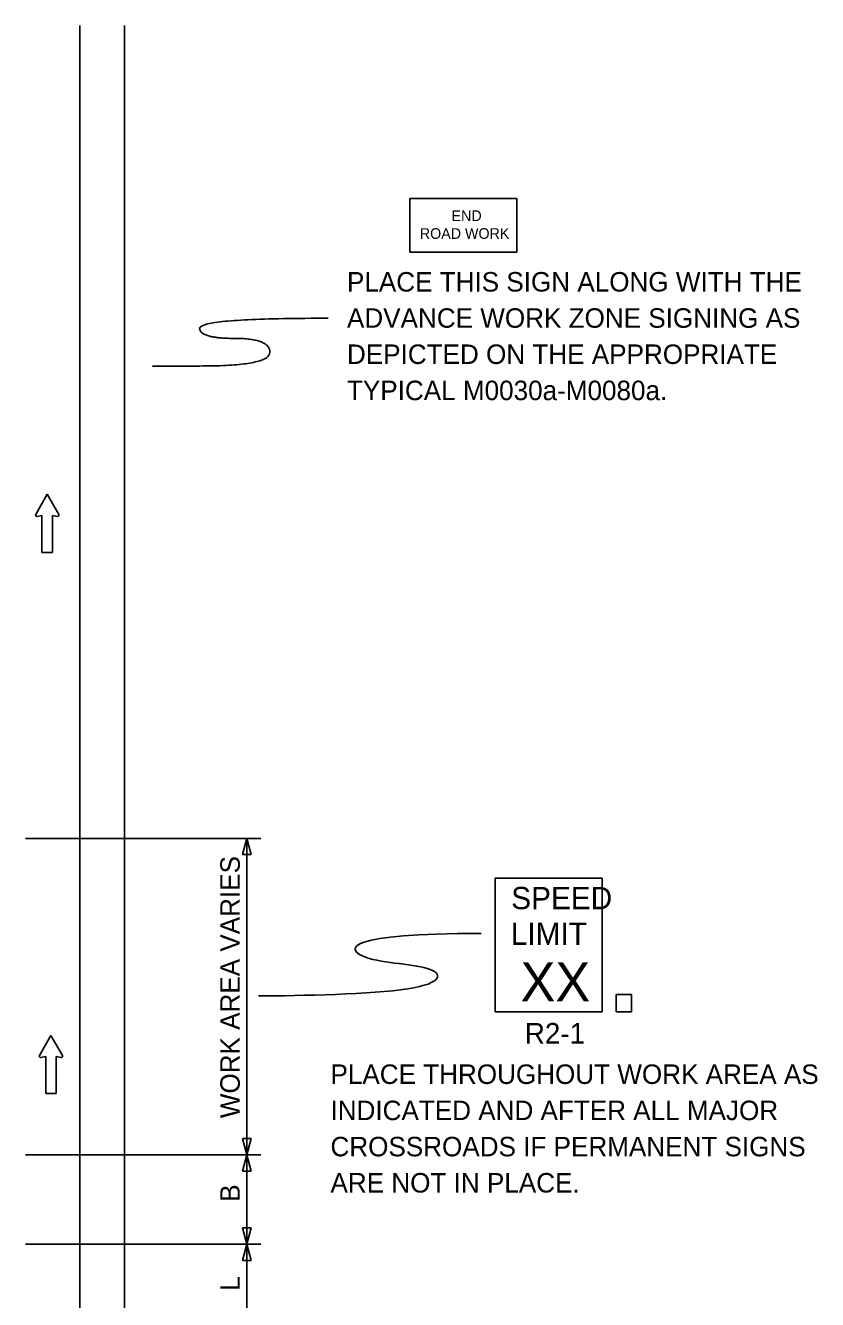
# Model space of a CAD drawing. Extents: x 16732 to 18475, y 6994 to 8262.
# Drawn here: x 17080.8 to 17365.2, y 7748.9 to 8206.5 of the extents above; entities that cross this region are included whole.
import ezdxf

# ---------------------------------------------------------------- set-up
doc = ezdxf.new("R2010")
doc.units = 0
for name, color, linetype in [('MT_SCRATCH_LEVEL_E', 7, 'Continuous'), ('PAVT_EDGE_EX', 7, 'Continuous'), ('TRAFFIC_SIGNS_PR', 7, 'Continuous'), ('TYPICAL_TEXT_DIMEN_PR', 7, 'Continuous')]:
    doc.layers.add(name, color=color, linetype=linetype)

msp = doc.modelspace()

# ---------------------------------------------------------------- linework, layer by layer
at = {"layer": 'MT_SCRATCH_LEVEL_E'}
for p, q in [((17088.58, 8038.11), (17084.47, 8030.87)), ((17088.58, 8038.11), (17084.47, 8030.87)), ((17092.73, 8030.87), (17088.58, 8038.11)), ((17092.73, 8030.87), (17088.58, 8038.11)), ((17084.95, 8030.19), (17086.73, 8030.5)), ((17084.95, 8030.19), (17086.73, 8030.5)), ((17086.73, 8030.5), (17086.73, 8017.24)), ((17086.73, 8030.5), (17086.73, 8017.24)), ((17090.47, 8017.24), (17090.47, 8030.5)), ((17090.47, 8030.5), (17092.25, 8030.19)), ((17090.47, 8017.24), (17090.47, 8030.5)), ((17090.47, 8030.5), (17092.25, 8030.19)), ((17086.73, 8017.24), (17090.47, 8017.24)), ((17086.73, 8017.24), (17090.47, 8017.24)), ((17089.92, 7843.78), (17085.81, 7836.54)), ((17089.92, 7843.78), (17085.81, 7836.54)), ((17094.07, 7836.54), (17089.92, 7843.78)), ((17094.07, 7836.54), (17089.92, 7843.78)), ((17086.29, 7835.86), (17088.07, 7836.17)), ((17086.29, 7835.86), (17088.07, 7836.17)), ((17088.07, 7836.17), (17088.07, 7822.91)), ((17088.07, 7836.17), (17088.07, 7822.91)), ((17091.81, 7822.91), (17091.81, 7836.17)), ((17091.81, 7836.17), (17093.59, 7835.86)), ((17091.81, 7822.91), (17091.81, 7836.17)), ((17091.81, 7836.17), (17093.59, 7835.86)), ((17088.07, 7822.91), (17091.81, 7822.91)), ((17088.07, 7822.91), (17091.81, 7822.91))]:
    msp.add_line(p, q, dxfattribs=at)
for centre, start, end in [((17084.88, 8030.65), 150.4248, 279.9638), ((17084.88, 8030.65), 150.4248, 279.9638), ((17092.32, 8030.65), 260.0362, 29.7731), ((17092.32, 8030.65), 260.0362, 29.7731), ((17086.22, 7836.32), 150.4248, 279.9638), ((17086.22, 7836.32), 150.4248, 279.9638), ((17093.66, 7836.32), 260.0362, 29.7731), ((17093.66, 7836.32), 260.0362, 29.7731)]:
    msp.add_arc(centre, 0.463, start, end, dxfattribs=at)
at = {"layer": 'PAVT_EDGE_EX'}
for p, q in [((17100.31, 8206.5), (17100.31, 7350.48)), ((17116.31, 8206.5), (17116.31, 7350.48))]:
    msp.add_line(p, q, dxfattribs=at)
at = {"layer": 'TRAFFIC_SIGNS_PR'}
for p, q in [((17249.42, 7900.24), (17287.82, 7900.24)), ((17249.42, 7852.24), (17249.42, 7900.24)), ((17287.82, 7852.24), (17287.82, 7900.24)), ((17249.42, 7852.24), (17287.82, 7852.24))]:
    msp.add_line(p, q, dxfattribs=at)
for points in [[(17218.77, 8125.12), (17257.17, 8125.12), (17257.17, 8144.32), (17218.77, 8144.32)], [(17292.84, 7852.24), (17298.43, 7852.24), (17298.43, 7858.41), (17292.84, 7858.41)]]:
    msp.add_lwpolyline(points, close=True, dxfattribs=at)
at = {"layer": 'TYPICAL_TEXT_DIMEN_PR'}
for p, q in [((17165.31, 7914.55), (17080.81, 7914.55)), ((17158.74, 7908.69), (17160.31, 7914.55)), ((17160.31, 7800.83), (17160.31, 7914.55)), ((17160.31, 7914.55), (17161.88, 7908.69)), ((17160.31, 7908.69), (17158.74, 7908.69)), ((17161.88, 7908.69), (17160.31, 7908.69)), ((17160.31, 7800.83), (17158.74, 7806.69)), ((17158.74, 7806.69), (17160.31, 7806.69)), ((17160.31, 7806.69), (17161.88, 7806.69)), ((17161.88, 7806.69), (17160.31, 7800.83)), ((17165.31, 7800.83), (17080.81, 7800.83)), ((17158.74, 7794.97), (17160.31, 7800.83)), ((17160.31, 7768.77), (17160.31, 7800.83)), ((17160.31, 7800.83), (17161.88, 7794.97)), ((17160.31, 7794.97), (17158.74, 7794.97)), ((17161.88, 7794.97), (17160.31, 7794.97)), ((17160.31, 7768.77), (17158.74, 7774.63)), ((17158.74, 7774.63), (17160.31, 7774.63)), ((17160.31, 7774.63), (17161.88, 7774.63)), ((17161.88, 7774.63), (17160.31, 7768.77)), ((17165.31, 7768.77), (17080.81, 7768.77)), ((17158.74, 7762.91), (17160.31, 7768.77)), ((17160.31, 7768.77), (17161.88, 7762.91)), ((17160.31, 7738.19), (17160.31, 7768.77)), ((17160.31, 7762.91), (17158.74, 7762.91)), ((17161.88, 7762.91), (17160.31, 7762.91))]:
    msp.add_line(p, q, dxfattribs=at)
for points, degree in [([(17189.47, 8101.36), (17143.38, 8101.36), (17143.38, 8094.1), (17168.56, 8094.1), (17168.56, 8084.19), (17118.91, 8084.19), (17129.95, 8084.19)], 2), ([(17244.4, 7880.39), (17195.93, 7880.39), (17195.93, 7869.64), (17230.85, 7869.64), (17230.85, 7858.92), (17179.53, 7858.04), (17164.41, 7857.94)], 3)]:
    msp.add_open_spline(points, degree=degree, dxfattribs=at)

# ---------------------------------------------------------------- texts
at = {"layer": 'TRAFFIC_SIGNS_PR'}
for s, height, p in [('END', 3.831, (17233.77, 8136.25)), ('ROAD WORK', 3.831, (17222.38, 8129.87)), ('PLACE THIS SIGN ALONG WITH THE', 7, (17196.23, 8110.93)), ('ADVANCE WORK ZONE SIGNING AS', 7, (17196.23, 8097.93)), ('DEPICTED ON THE APPROPRIATE', 7, (17196.23, 8084.93)), ('TYPICAL M0030a-M0080a.', 7, (17196.23, 8071.93)), ('SPEED', 8, (17255.19, 7889.1)), ('LIMIT', 8, (17255.03, 7876.3)), ('XX', 14.031, (17258.53, 7855.99)), ('R2-1', 7.44, (17260.1, 7840.8)), ('PLACE THROUGHOUT WORK AREA AS', 7, (17190.31, 7826.34)), ('INDICATED AND AFTER ALL MAJOR', 7, (17190.31, 7813.34)), ('CROSSROADS IF PERMANENT SIGNS', 7, (17190.31, 7800.34)), ('ARE NOT IN PLACE.', 7, (17190.31, 7787.34))]:
    msp.add_text(s, height=height, dxfattribs=at).set_placement(p)
at = {"layer": 'TYPICAL_TEXT_DIMEN_PR'}
for s, p in [('WORK AREA VARIES', (17157.75, 7814.05)), ('B', (17157.75, 7784.03)), ('L', (17157.75, 7752.06))]:
    msp.add_text(s, height=7, rotation=90, dxfattribs=at).set_placement(p)

doc.saveas('drawing.dxf')
